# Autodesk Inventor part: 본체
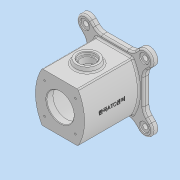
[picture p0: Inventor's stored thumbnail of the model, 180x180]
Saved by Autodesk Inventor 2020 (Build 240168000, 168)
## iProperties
Created: 2022-01
Part Number: 본체
Material: 일반
Document SubType Name: Modeling
Designer: user
Density: 1 g/cm^3
Appearance: 기본값
Mass: 459.034 g
Surface Area: 909.169 cm^2
Volume: 459.034 cm^3
Author: user
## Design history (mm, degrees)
sketch "스케치1"
  geometry: L1 (-32.942, -45)-(32.942, -45); L2 (32.942, 45)-(-32.942, 45); L3 (-45, -45)-(45, 45); L4 (45, -45)-(-45, 45); A1 r 90 centre (45, 0) between (-32.942, 45) and (-32.942, -45); A2 r 90 centre (-45, 0) between (32.942, -45) and (32.942, 45); 5 further points
  constraints: 8 end point, 6 point on circle, 3 midpoint, 2 centre point, 2 coincident, 2 vertical alignment, 1 horizontal, 1 parallel, 1 perpendicular
  dimensions: "d0" = 90 distance of L4.end L3.end; "d1" = 90 distance of L3.end L4.start; "d10" = 90 radius of A2; "d11" = 90 radius of A1; "d12" = 45 deg angle of L2 L3; "d13" = 90 distance between parallel lines of L2 L1; "d14" = 45 distance from line of point (0, 0) L2; "d15" = 0 distance from line of L3.end L2; "d16" = 31.81981 distance from line of point (45, 0) L3; "d17" = 31.81981 distance from line of A1.centre L3; "d18" = 31.81981 distance from line of point (0, -45) L3; "d19" = 90 distance from line of L3.start L2
extrude "돌출1" new body sketch "스케치1" distance "d3" = 100; taper "d4" = 0 deg
sketch "스케치2"
  geometry: L1 (-53, -53)-(53, -53); L2 (53, -53)-(53, 53); L3 (53, 53)-(-53, 53); L4 (-53, 53)-(-53, -53); L5 (-53, -53)-(53, 53); L6 (53, -53)-(-53, 53); L7 (54.447, -54.447)-(-54.447, 54.447); L8 (65.054, -43.841)-(-43.841, 65.054); L9 (-65.054, 43.841)-(43.841, -65.054); L10 (-54.447, -54.447)-(54.447, 54.447); L11 (-43.841, -65.054)-(65.054, 43.841); L12 (43.841, 65.054)-(-65.054, -43.841); A1 r 77 centre (0, 0) between (-54.447, 54.447) and (54.447, 54.447); A2 r 15 centre (54.447, -54.447) between (43.841, -65.054) and (65.054, -43.841); A3 r 15 centre (-54.447, 54.447) between (-43.841, 65.054) and (-65.054, 43.841); A4 r 15 centre (-54.447, -54.447) between (-65.054, -43.841) and (-43.841, -65.054); A5 r 15 centre (54.447, 54.447) between (65.054, 43.841) and (43.841, 65.054); 9 further points
  constraints: 28 end point, 10 point on circle, 8 tangent, 5 centre point, 4 midpoint, 4 parallel, 2 point on line, 1 coincident, 1 horizontal, 1 perpendicular
  dimensions: "d5" = 106 distance of L3.end L2.end; "d6" = 106 distance of L2.end L1.end; "d7" = 154 diameter of A1; "d8" = 30 diameter of A3; "d9" = 30 diameter of A5
extrude "돌출2" join sketch "스케치2" distance "d20" = 10; taper "d21" = 0 deg
node "작업 평면1"
sketch "스케치3"
  geometry: L1 (31.787, -10)-(-31.787, -10) reference; L2 (31.787, 0)-(-31.787, 0) reference; C1 r 20 at (0, 50); 2 further points
  constraints: 1 centre point, 1 midpoint, 1 vertical alignment
  dimensions: "d23" = 40 diameter of C1; "d24" = 50 distance of point (0, 0) C1.centre
extrude "돌출3" join sketch "스케치3" stored distance "d25" = 10; taper "d26" = 15 deg
sketch "스케치4"
  geometry: C1 r 20 at (0, 0) reference; C2 r 15 at (0, 0); 1 further point
  constraints: 1 centre point, 1 coincident
  dimensions: "d27" = 30 diameter of C2
extrude "돌출4" cut sketch "스케치4" distance "d28" = 5; taper "d29" = 0 deg
sketch "스케치5"
  geometry: C1 r 15 at (0, 0) reference; C2 r 15 at (0, 0) reference; C3 r 12 at (0, 0); 1 further point
  constraints: 1 centre point, 1 coincident
  dimensions: "d30" = 24 diameter of C3
extrude "돌출5" cut sketch "스케치5" distance "d31" = 47.5; taper "d32" = 0 deg
sketch "스케치6"
  geometry: C1 r 25 at (0, 0); 1 further point
  constraints: 1 centre point, 1 coincident
  dimensions: "d33" = 50 diameter of C1
extrude "돌출6" cut sketch "스케치6" distance "d34" = 12; taper "d35" = 0 deg
sketch "스케치7"
  geometry: C1 r 37 at (0, 0); 1 further point
  constraints: 1 centre point, 1 coincident
  dimensions: "d36" = 74 diameter of C1
extrude "돌출7" cut sketch "스케치7" distance "d37" = 86; taper "d38" = 0 deg
sketch "스케치8"
  geometry: C1 r 25 at (0, 0); 1 further point
  constraints: 1 centre point, 1 coincident
  dimensions: "d39" = 50 diameter of C1
extrude "돌출8" cut sketch "스케치8" distance "d40" = 12; taper "d41" = 0 deg
sketch "스케치9"
  geometry: L1 (53, -31.787)-(65.054, -43.841) reference; L2 (53, 31.787)-(53, -31.787) reference; L3 (65.054, 43.841)-(53, 31.787) reference; L4 (31.787, 53)-(43.841, 65.054) reference; L5 (-31.787, 53)-(31.787, 53) reference; L6 (-43.841, 65.054)-(-31.787, 53) reference; L7 (-53, 31.787)-(-65.054, 43.841) reference; L8 (-53, -31.787)-(-53, 31.787) reference; L9 (-65.054, -43.841)-(-53, -31.787) reference; L10 (-31.787, -53)-(-43.841, -65.054) reference; L11 (31.787, -53)-(-31.787, -53) reference; L12 (43.841, -65.054)-(31.787, -53) reference; L13 (32.942, 45)-(-32.942, 45) reference; L14 (-32.942, -45)-(32.942, -45) reference; A1 r 15 centre (54.447, 54.447) between (65.054, 43.841) and (43.841, 65.054) reference; A2 r 15 centre (-54.447, 54.447) between (-43.841, 65.054) and (-65.054, 43.841) reference; A3 r 15 centre (-54.447, -54.447) between (-65.054, -43.841) and (-43.841, -65.054) reference; A4 r 15 centre (54.447, -54.447) between (43.841, -65.054) and (65.054, -43.841) reference; A5 r 90 centre (-45, 0) between (32.942, -45) and (32.942, 45) reference; A6 r 90 centre (45, 0) between (-32.942, 45) and (-32.942, -45) reference; 1 further point
  node "투영된 루프3"
hole "구멍1" sketch "스케치9" diameter "d42" = 9; stored, may be unused: countersink angle "d46" = 90 deg, drill point angle "d48" = 118 deg; dims "d43" = 33, "d44" = 18, "d45" = 2, "d47" = 34.05
hole "구멍2" sketch "스케치9" diameter "d49" = 9; stored, may be unused: countersink angle "d53" = 90 deg, drill point angle "d55" = 118 deg; dims "d50" = 33, "d51" = 18, "d52" = 2, "d54" = 34.05
hole "구멍3" sketch "스케치9" diameter "d56" = 9; stored, may be unused: countersink angle "d60" = 90 deg, drill point angle "d62" = 118 deg; dims "d57" = 33, "d58" = 18, "d59" = 2, "d61" = 34.05
hole "구멍4" sketch "스케치9" diameter "d63" = 9; stored, may be unused: countersink angle "d67" = 90 deg, drill point angle "d69" = 118 deg; dims "d64" = 33, "d65" = 18, "d66" = 2, "d68" = 34.05
sketch "스케치10" dims "d70" = 80
  geometry: L1 (-32.942, -45)-(32.942, -45) reference; L2 (32.942, 45)-(-32.942, 45) reference; L3 (0, 0)-(-79.741, 79.741); L4 (0, 0)-(78.475, 78.475); L5 (0, 0)-(0, 76.338); C1 r 25 at (0, 0) reference; A1 r 90 centre (-45, 0) between (32.942, -45) and (32.942, 45) reference; A2 r 90 centre (45, 0) between (-32.942, 45) and (-32.942, -45) reference; 2 further points
  constraints: 6 end point, 1 coincident, 1 point on line, 1 vertical, 3 other
  dimensions: "d71" = 45 deg angle of L5 L3; "d72" = 45 deg angle of L4 L5
hole "구멍5" sketch "스케치10" at (-28.284, 28.284) diameter "d73" = 3.242; stored, may be unused: countersink angle "d77" = 90 deg, drill point angle "d79" = 118 deg; dims "d74" = 8, "d75" = 18, "d76" = 2, "d78" = 10
sketch "스케치11"
  geometry: C1 r 1.621 at (-28.284, 28.284) reference; 1 further point
hole "구멍6" sketch "스케치11" at (-28.284, 28.284) diameter "d83" = 3.242; stored, may be unused: countersink angle "d87" = 90 deg, drill point angle "d89" = 118 deg; dims "d84" = 8, "d85" = 18, "d86" = 2, "d88" = 10
fillet "모깎기1" dims "d93" = 20
chamfer "모따기1" distance "d94" = 1; stored, may be unused: second distance "d95" = 2, angle "d96" = 45 deg
chamfer "모따기2" distance "d97" = 1; stored, may be unused: second distance "d98" = 2, angle "d99" = 45 deg
fillet "모깎기2" dims "d100" = 3
fillet "모깎기3" dims "d101" = 3
fillet "모깎기4" dims "d102" = 3
fillet "모깎기5" dims "d103" = 3
sketch "스케치12"
  geometry: L1 (53, 30)-(53, 70) reference; L2 (-26, -10)-(26, -10) reference; 2 further points
  constraints: 1 other
  dimensions: "d104" = 60 distance from line of L2 point (0, 50); "d105" = 53 distance from line of point (0, 50) L1
feature "엠보싱1" sketch "스케치12" dims "d0" = 90, "d1" = 90, "d5" = 106, "d6" = 106, "d7" = 154, "d8" = 30, "d9" = 30, "d10" = 90, "d11" = 90, "d12" = 45 deg, "d13" = 90, "d14" = 45, "d15" = 0, "d16" = 31.81981, "d17" = 31.81981, "d18" = 31.81981, "d19" = 90, "d106" = 0.5, "d107" = 0
fillet "모깎기6" dims "d108" = 3
node "솔리드1"
pattern_circular "원형 패턴1" dims angle "d81" = 360 deg
pattern_circular "원형 패턴2" dims angle "d91" = 360 deg
node "투영된 루프1"
node "투영된 루프2"
node "투영된 루프4"
feature "A9D066F2-1C7D-4E18-AEED-F7BC21143FA4" dims "d42" = 9, "d43" = 33, "d44" = 18, "d45" = 2, "d46" = 90 deg, "d47" = 34.05, "d48" = 118 deg
other parameters: "d22" = 53
